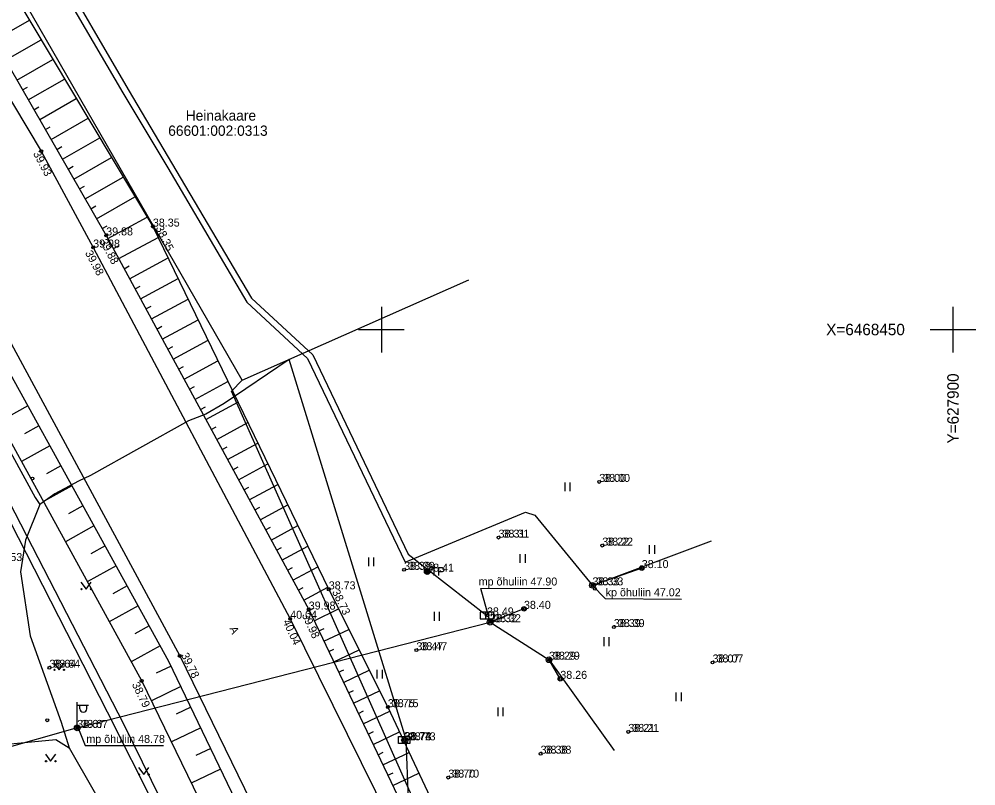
# Model space of a CAD drawing. Extents: x 627548 to 628052, y 6467984 to 6468802.
# Drawn here: x 627818.3 to 627902, y 6468410.1 to 6468477.2 of the extents above; entities that cross this region are included whole.
import ezdxf

# ---------------------------------------------------------------- set-up
doc = ezdxf.new("R2010")
doc.units = 0
for name, color, linetype in [('ABIJOONIS', 7, 'Continuous'), ('ELRAJATISMP', 7, 'Continuous'), ('HALJASTUS', 7, 'Continuous'), ('KORGUS-EH2000', 7, 'Continuous'), ('KPKAABEL', 7, 'Continuous'), ('KPOHULIIN', 7, 'Continuous'), ('MOOTKORG-EH2000', 7, 'Continuous'), ('MOOTMPUNKT', 7, 'Continuous'), ('MPKAABEL', 7, 'Continuous'), ('MPOHULIIN', 7, 'Continuous'), ('PIIR', 7, 'Continuous'), ('POST', 7, 'Continuous'), ('RELJEEF', 7, 'Continuous'), ('SIOHULIIN', 7, 'Continuous'), ('SIRAJATIS', 7, 'Continuous'), ('SITRASS', 7, 'Continuous'), ('TEE', 7, 'Continuous'), ('VORK', 7, 'Continuous')]:
    doc.layers.add(name, color=color, linetype=linetype)

msp = doc.modelspace()

# ---------------------------------------------------------------- linework, layer by layer
at = {"layer": 'ABIJOONIS'}
for points in [[(627859.51, 6468424.378), (627858.71, 6468427.326), (627864.891, 6468427.37)], [(627868.465, 6468427.605), (627869.568, 6468426.466), (627876.261, 6468426.388)], [(627823.446, 6468415.185), (627824.073, 6468413.598), (627830.931, 6468413.598)]]:
    msp.add_lwpolyline(points, dxfattribs=at)
at = {"layer": 'ELRAJATISMP'}
for p, q in [((627859.831, 6468425.271), (627858.637, 6468425.271)), ((627858.637, 6468425.271), (627858.637, 6468424.675)), ((627859.098, 6468425.271), (627859.098, 6468424.675)), ((627859.37, 6468425.271), (627859.37, 6468424.675)), ((627859.831, 6468424.675), (627859.831, 6468425.271)), ((627858.637, 6468424.675), (627859.831, 6468424.675))]:
    msp.add_line(p, q, dxfattribs=at)
at = {"layer": 'HALJASTUS'}
for p, q in [((627866.036, 6468436.597), (627866.036, 6468435.835)), ((627866.491, 6468436.597), (627866.491, 6468435.835)), ((627873.429, 6468431.134), (627873.429, 6468430.373)), ((627873.884, 6468431.134), (627873.884, 6468430.373)), ((627862.112, 6468430.338), (627862.112, 6468429.577)), ((627862.567, 6468430.338), (627862.567, 6468429.577)), ((627848.862, 6468430.053), (627848.862, 6468429.292)), ((627849.317, 6468430.053), (627849.317, 6468429.292)), ((627823.7, 6468427.88), (627824.164, 6468427.273)), ((627824.164, 6468427.273), (627824.609, 6468427.88)), ((627854.606, 6468425.274), (627854.606, 6468424.513)), ((627855.061, 6468425.274), (627855.061, 6468424.513)), ((627869.448, 6468423.055), (627869.448, 6468422.294)), ((627869.903, 6468423.055), (627869.903, 6468422.294)), ((627821.346, 6468420.818), (627821.809, 6468420.212)), ((627821.809, 6468420.212), (627822.255, 6468420.818)), ((627849.601, 6468420.21), (627849.601, 6468419.449)), ((627850.056, 6468420.21), (627850.056, 6468419.449)), ((627875.76, 6468418.218), (627875.76, 6468417.457)), ((627876.215, 6468418.218), (627876.215, 6468417.457)), ((627860.179, 6468416.91), (627860.179, 6468416.148)), ((627860.634, 6468416.91), (627860.634, 6468416.148)), ((627820.606, 6468412.816), (627821.069, 6468412.209)), ((627821.069, 6468412.209), (627821.515, 6468412.816)), ((627828.749, 6468411.659), (627829.213, 6468411.052)), ((627829.213, 6468411.052), (627829.658, 6468411.659))]:
    msp.add_line(p, q, dxfattribs=at)
for centre in [(627823.763, 6468427.273), (627824.591, 6468427.273), (627821.408, 6468420.212), (627822.237, 6468420.212), (627820.668, 6468412.209), (627821.497, 6468412.209), (627828.812, 6468411.052), (627829.64, 6468411.052)]:
    msp.add_circle(centre, 0.055, dxfattribs=at)
at = {"layer": 'KORGUS-EH2000'}
for centre in [(627820.25, 6468465.607), (627832.36, 6468421.427), (627829.03, 6468419.237), (627820.77, 6468415.797)]:
    msp.add_circle(centre, 0.125, dxfattribs=at)
at = {"layer": 'KPKAABEL'}
msp.add_lwpolyline([(627783.664, 6468533.605), (627793.043, 6468521.367), (627800.254, 6468512.234), (627809.598, 6468500.188), (627812.996, 6468495.066), (627814.512, 6468492.199), (627820.805, 6468482.012), (627827.375, 6468470.727), (627831.316, 6468464.148), (627838.215, 6468452.395), (627843.543, 6468447.449), (627852.07, 6468429.637), (627862.617, 6468434.004), (627863.434, 6468433.738), (627868.465, 6468427.605)], dxfattribs=at)
at = {"layer": 'KPOHULIIN'}
msp.add_lwpolyline([(627868.465, 6468427.605), (627878.875, 6468431.498)], dxfattribs=at)
at = {"layer": 'MOOTMPUNKT'}
for centre in [(627830.011, 6468459.01), (627825.927, 6468458.237), (627824.787, 6468457.176), (627819.485, 6468436.954), (627869.054, 6468436.658), (627860.248, 6468431.782), (627869.319, 6468431.085), (627851.985, 6468428.963), (627854.009, 6468428.806), (627872.776, 6468429.115), (627845.394, 6468427.254), (627868.465, 6468427.605), (627868.669, 6468427.3), (627843.642, 6468425.485), (627862.471, 6468425.547), (627842.022, 6468424.68), (627859.234, 6468424.973), (627859.51, 6468424.378), (627859.614, 6468424.591), (627870.333, 6468423.953), (627853.061, 6468421.927), (627864.663, 6468421.096), (627820.956, 6468420.393), (627878.967, 6468420.856), (627865.651, 6468419.421), (627850.56, 6468416.941), (627823.391, 6468415.126), (627823.446, 6468415.185), (627871.595, 6468414.773), (627851.989, 6468414.072), (627852.048, 6468414.037), (627863.924, 6468412.869), (627855.853, 6468410.777)]:
    msp.add_circle(centre, 0.125, dxfattribs=at)
at = {"layer": 'MPKAABEL'}
msp.add_lwpolyline([(627775.609, 6468546.285), (627774.98, 6468546.789), (627774.719, 6468546.18), (627774.691, 6468545.898), (627776.109, 6468544.039), (627784.09, 6468533.941), (627791.949, 6468523.77), (627800.68, 6468512.578), (627810.039, 6468500.512), (627813.461, 6468495.352), (627814.988, 6468492.48), (627821.281, 6468482.301), (627827.852, 6468471.012), (627838.641, 6468452.75), (627843.988, 6468447.781), (627852.328, 6468430.34), (627859.234, 6468424.973)], dxfattribs=at)
at = {"layer": 'MPOHULIIN'}
for q in [(627859.51, 6468424.378), (627808.24, 6468410.853)]:
    msp.add_line((627823.391, 6468415.126), q, dxfattribs=at)
at = {"layer": 'PIIR'}
for p, q in [((627837.82, 6468445.56), (627818.92, 6468478.42)), ((627837.82, 6468445.56), (627857.65, 6468454.352)), ((627836.88, 6468444.6), (627837.82, 6468445.56)), ((627893.5, 6468317.49), (627836.88, 6468444.6)), ((627816.81, 6468434.6), (627826.02, 6468416.53)), ((627826.02, 6468416.53), (627834.21, 6468400.21))]:
    msp.add_line(p, q, dxfattribs=at)
at = {"layer": 'POST'}
for p, q in [((627854.368, 6468429.153), (627854.835, 6468429.153)), ((627854.601, 6468429.153), (627854.601, 6468428.453)), ((627855.001, 6468429.153), (627855.001, 6468428.453)), ((627823.393, 6468415.373), (627823.393, 6468417.373)), ((627823.393, 6468417.123), (627824.393, 6468417.123)), ((627823.62, 6468416.802), (627823.62, 6468417.123)), ((627824.232, 6468416.802), (627824.232, 6468417.123))]:
    msp.add_line(p, q, dxfattribs=at)
for points in [[(627855.001, 6468429.153), (627855.301, 6468429.153), (627855.401, 6468429.12), (627855.435, 6468429.087), (627855.468, 6468429.02), (627855.468, 6468428.92), (627855.435, 6468428.853), (627855.401, 6468428.82), (627855.301, 6468428.787), (627855.001, 6468428.787)], [(627872.776, 6468429.115), (627868.465, 6468427.605)], [(627862.471, 6468425.547), (627859.51, 6468424.378)], [(627865.651, 6468419.421), (627864.663, 6468421.096)]]:
    msp.add_lwpolyline(points, dxfattribs=at)
for centre, radius in [((627854.009, 6468428.806), 0.25), ((627854.009, 6468428.806), 0.225), ((627854.009, 6468428.806), 0.2), ((627854.009, 6468428.806), 0.175), ((627854.009, 6468428.806), 0.15), ((627854.009, 6468428.806), 0.125), ((627854.009, 6468428.806), 0.1), ((627854.009, 6468428.806), 0.075), ((627854.009, 6468428.806), 0.05), ((627854.009, 6468428.806), 0.025), ((627872.776, 6468429.115), 0.2), ((627868.465, 6468427.605), 0.25), ((627862.471, 6468425.547), 0.2), ((627859.51, 6468424.378), 0.25), ((627864.663, 6468421.096), 0.25), ((627864.663, 6468421.096), 0.0234), ((627865.651, 6468419.421), 0.2), ((627823.391, 6468415.126), 0.25), ((627852.048, 6468414.037), 0.25)]:
    msp.add_circle(centre, radius, dxfattribs=at)
msp.add_arc((627823.926, 6468416.802), 0.306, 180, 0, dxfattribs=at)
at = {"layer": 'RELJEEF'}
for p, q in [((627816.126, 6468475.31), (627819.206, 6468477.079)), ((627817.121, 6468473.576), (627820.233, 6468475.362)), ((627818.117, 6468471.841), (627821.26, 6468473.645)), ((627819.113, 6468470.107), (627822.286, 6468471.929)), ((627818.615, 6468470.974), (627819.049, 6468471.223)), ((627820.109, 6468468.372), (627823.313, 6468470.212)), ((627819.611, 6468469.24), (627820.044, 6468469.489)), ((627821.104, 6468466.638), (627824.339, 6468468.495)), ((627820.606, 6468467.505), (627821.04, 6468467.754)), ((627822.1, 6468464.903), (627825.366, 6468466.778)), ((627821.602, 6468465.771), (627822.036, 6468466.02)), ((627823.096, 6468463.169), (627826.392, 6468465.061)), ((627822.598, 6468464.036), (627823.032, 6468464.285)), ((627824.092, 6468461.434), (627827.419, 6468463.345)), ((627823.594, 6468462.302), (627824.027, 6468462.551)), ((627825.087, 6468459.7), (627828.446, 6468461.628)), ((627824.589, 6468460.567), (627825.023, 6468460.816)), ((627826.076, 6468457.961), (627829.523, 6468459.826)), ((627825.585, 6468458.833), (627826.019, 6468459.081)), ((627827.028, 6468456.202), (627830.469, 6468458.064)), ((627826.552, 6468457.082), (627826.992, 6468457.32)), ((627827.979, 6468454.443), (627831.342, 6468456.262)), ((627827.503, 6468455.323), (627827.943, 6468455.561)), ((627828.455, 6468453.564), (627828.895, 6468453.801)), ((627828.931, 6468452.684), (627832.215, 6468454.46)), ((627829.406, 6468451.804), (627829.846, 6468452.042)), ((627829.882, 6468450.925), (627833.088, 6468452.659)), ((627830.834, 6468449.166), (627833.96, 6468450.857)), ((627830.358, 6468450.045), (627830.798, 6468450.283)), ((627831.785, 6468447.406), (627834.833, 6468449.055)), ((627831.309, 6468448.286), (627831.749, 6468448.524)), ((627832.737, 6468445.647), (627835.706, 6468447.253)), ((627832.261, 6468446.527), (627832.701, 6468446.765)), ((627833.688, 6468443.888), (627836.579, 6468445.452)), ((627833.212, 6468444.768), (627833.652, 6468445.006)), ((627819.059, 6468443.315), (627816.59, 6468441.952)), ((627834.164, 6468443.009), (627834.604, 6468443.246)), ((627834.64, 6468442.129), (627837.452, 6468443.65)), ((627820.026, 6468441.565), (627818.788, 6468440.881)), ((627835.115, 6468441.249), (627835.555, 6468441.487)), ((627835.591, 6468440.37), (627838.324, 6468441.848)), ((627820.992, 6468439.814), (627818.511, 6468438.444)), ((627836.067, 6468439.49), (627836.507, 6468439.728)), ((627836.543, 6468438.611), (627839.197, 6468440.046)), ((627821.959, 6468438.063), (627820.715, 6468437.376)), ((627837.018, 6468437.731), (627837.458, 6468437.969)), ((627837.494, 6468436.852), (627840.07, 6468438.245)), ((627822.926, 6468436.312), (627820.433, 6468434.935)), ((627837.97, 6468435.972), (627838.41, 6468436.21)), ((627838.446, 6468435.092), (627840.943, 6468436.443)), ((627823.892, 6468434.561), (627822.643, 6468433.871)), ((627838.921, 6468434.213), (627839.361, 6468434.451)), ((627839.397, 6468433.333), (627841.816, 6468434.641)), ((627824.859, 6468432.81), (627822.354, 6468431.427)), ((627840.349, 6468431.574), (627842.688, 6468432.84)), ((627839.873, 6468432.454), (627840.313, 6468432.691)), ((627825.826, 6468431.059), (627824.57, 6468430.366)), ((627840.824, 6468430.694), (627841.264, 6468430.932)), ((627841.3, 6468429.815), (627843.561, 6468431.038)), ((627826.792, 6468429.308), (627824.276, 6468427.919)), ((627841.776, 6468428.935), (627842.216, 6468429.173)), ((627842.252, 6468428.056), (627844.434, 6468429.236)), ((627827.759, 6468427.558), (627826.498, 6468426.861)), ((627842.727, 6468427.176), (627843.167, 6468427.414)), ((627843.203, 6468426.297), (627845.307, 6468427.434)), ((627828.726, 6468425.807), (627826.197, 6468424.411)), ((627843.675, 6468425.415), (627844.127, 6468425.631)), ((627844.106, 6468424.513), (627846.254, 6468425.538)), ((627829.692, 6468424.056), (627828.425, 6468423.356)), ((627844.537, 6468423.61), (627844.988, 6468423.826)), ((627844.968, 6468422.708), (627847.15, 6468423.749)), ((627830.659, 6468422.305), (627828.119, 6468420.902)), ((627845.399, 6468421.805), (627845.85, 6468422.021)), ((627845.829, 6468420.903), (627848.045, 6468421.961)), ((627831.601, 6468420.542), (627830.301, 6468419.917)), ((627846.26, 6468420.001), (627846.711, 6468420.216)), ((627846.691, 6468419.098), (627848.941, 6468420.172)), ((627832.467, 6468418.739), (627829.877, 6468417.494)), ((627847.122, 6468418.196), (627847.573, 6468418.411)), ((627847.553, 6468417.293), (627849.837, 6468418.384)), ((627833.334, 6468416.936), (627832.042, 6468416.316)), ((627847.983, 6468416.391), (627848.435, 6468416.606)), ((627848.414, 6468415.488), (627850.724, 6468416.591)), ((627834.2, 6468415.133), (627831.625, 6468413.896)), ((627848.845, 6468414.586), (627849.296, 6468414.801)), ((627849.276, 6468413.683), (627851.575, 6468414.781)), ((627835.066, 6468413.331), (627833.782, 6468412.714)), ((627849.707, 6468412.781), (627850.158, 6468412.996)), ((627850.137, 6468411.879), (627852.425, 6468412.971)), ((627835.932, 6468411.528), (627833.373, 6468410.298)), ((627850.568, 6468410.976), (627851.019, 6468411.191)), ((627850.999, 6468410.074), (627853.275, 6468411.16))]:
    msp.add_line(p, q, dxfattribs=at)
for points in [[(627773.759, 6468549.461), (627771.296, 6468547.152), (627771.109, 6468545.291), (627781.198, 6468531.285), (627796.852, 6468507.373), (627811.934, 6468482.612), (627825.927, 6468458.237), (627843.642, 6468425.485), (627854.711, 6468402.298), (627862.101, 6468385.395), (627866.289, 6468377.389), (627871.184, 6468377.936)], [(627772.366, 6468547.143), (627782.438, 6468532.945), (627799.726, 6468507.289), (627814.065, 6468485.677), (627830.011, 6468459.01), (627845.394, 6468427.254), (627850.56, 6468416.941), (627856.095, 6468405.157), (627864.813, 6468385.745), (627868.21, 6468378.879), (627870.923, 6468379.118)], [(627798.462, 6468458.953), (627803.154, 6468462.558), (627806.385, 6468462.787), (627809.612, 6468460.426), (627831.39, 6468420.981), (627849.758, 6468382.754), (627863.845, 6468351.725), (627866.293, 6468345.533)], [(627863.023, 6468347.157), (627861.127, 6468351.404), (627847.089, 6468382.059), (627829.031, 6468419.236), (627807.647, 6468458.279), (627806.821, 6468459.718), (627803.902, 6468460.271), (627798.462, 6468458.953)]]:
    msp.add_lwpolyline(points, dxfattribs=at)
at = {"layer": 'SIOHULIIN'}
for points in [[(627859.51, 6468424.378), (627864.663, 6468421.096)], [(627864.663, 6468421.096), (627870.364, 6468413.15)]]:
    msp.add_lwpolyline(points, dxfattribs=at)
at = {"layer": 'SIRAJATIS'}
msp.add_lwpolyline([(627851.489, 6468414.372), (627852.489, 6468414.372), (627852.489, 6468413.772), (627851.489, 6468413.772)], close=True, dxfattribs=at)
for centre, radius in [((627851.789, 6468414.072), 0.0304), ((627851.789, 6468414.072), 0.029), ((627851.789, 6468414.072), 0.0277), ((627851.789, 6468414.072), 0.0263), ((627851.789, 6468414.072), 0.0249), ((627851.789, 6468414.072), 0.0236), ((627851.789, 6468414.072), 0.0222), ((627851.789, 6468414.072), 0.0209), ((627851.789, 6468414.072), 0.0195), ((627851.789, 6468414.072), 0.0181), ((627851.789, 6468414.072), 0.0168), ((627851.789, 6468414.072), 0.0154), ((627851.789, 6468414.072), 0.014), ((627851.789, 6468414.072), 0.0127), ((627851.789, 6468414.072), 0.0113), ((627851.789, 6468414.072), 0.00996), ((627851.789, 6468414.072), 0.0086), ((627851.789, 6468414.072), 0.00724), ((627851.789, 6468414.072), 0.00587), ((627851.789, 6468414.072), 0.00451), ((627851.789, 6468414.072), 0.00315), ((627851.789, 6468414.072), 0.00179), ((627851.789, 6468414.072), 0.000426), ((627852.189, 6468414.072), 0.0304), ((627852.189, 6468414.072), 0.029), ((627852.189, 6468414.072), 0.0277), ((627852.189, 6468414.072), 0.0263), ((627852.189, 6468414.072), 0.0249), ((627852.189, 6468414.072), 0.0236), ((627852.189, 6468414.072), 0.0222), ((627852.189, 6468414.072), 0.0209), ((627852.189, 6468414.072), 0.0195), ((627852.189, 6468414.072), 0.0181), ((627852.189, 6468414.072), 0.0168), ((627852.189, 6468414.072), 0.0154), ((627852.189, 6468414.072), 0.014), ((627852.189, 6468414.072), 0.0127), ((627852.189, 6468414.072), 0.0113), ((627852.189, 6468414.072), 0.00996), ((627852.189, 6468414.072), 0.0086), ((627852.189, 6468414.072), 0.00724), ((627852.189, 6468414.072), 0.00587), ((627852.189, 6468414.072), 0.00451), ((627852.189, 6468414.072), 0.00315), ((627852.189, 6468414.072), 0.00179), ((627852.189, 6468414.072), 0.000426)]:
    msp.add_circle(centre, radius, dxfattribs=at)
at = {"layer": 'SITRASS'}
for points in [[(627757.217, 6468532.631), (627766.085, 6468521.026), (627772.396, 6468510.946), (627774.395, 6468507.251), (627778.965, 6468498.694), (627784.571, 6468489.044), (627791.177, 6468479.022), (627796.223, 6468473.32), (627799.931, 6468467.58), (627802.003, 6468462.412), (627804.987, 6468458.791), (627809.717, 6468452.583), (627813.499, 6468446.21), (627816.609, 6468440.925), (627819.703, 6468435.299), (627820.118, 6468434.673)], [(627757.269, 6468529.067), (627768.1, 6468513.354), (627774.946, 6468502.943), (627783.7, 6468488.286), (627791.516, 6468476.471), (627794.222, 6468472.86), (627799.922, 6468464.28), (627804.258, 6468458.3), (627808.24, 6468452.254), (627816.937, 6468435.872), (627827.445, 6468415.491), (627836.355, 6468397.304), (627844.956, 6468379.511), (627852.286, 6468362.282), (627856.189, 6468352.574), (627857.741, 6468350.531), (627858.742, 6468350.866)], [(627858.208, 6468326.11), (627860.012, 6468334.798), (627858.052, 6468342.909), (627856.848, 6468350.174), (627857.076, 6468352.201), (627855.207, 6468358.41), (627854.195, 6468363.46), (627853.606, 6468377.354), (627852.171, 6468414.124), (627841.938, 6468447.386), (627836.234, 6468443.524)], [(627836.234, 6468443.524), (627834.646, 6468442.578), (627833.128, 6468441.996), (627824.547, 6468437.221), (627823.498, 6468436.717), (627821.44, 6468435.608), (627820.118, 6468434.673), (627818.856, 6468431.558), (627818.43, 6468428.775), (627819.276, 6468423.196), (627821.974, 6468415.639), (627822.696, 6468413.373)], [(627810.98, 6468412.92), (627816.008, 6468413.596), (627821.508, 6468414.106), (627822.696, 6468413.373), (627824.885, 6468409.551), (627827.286, 6468404.81), (627834.996, 6468390.373), (627839.865, 6468381.11), (627848.975, 6468360.983), (627852.832, 6468354.033), (627854.055, 6468352.951), (627855.398, 6468352.508), (627856.692, 6468352.349), (627857.78, 6468352.478), (627859.022, 6468352.51)]]:
    msp.add_lwpolyline(points, dxfattribs=at)
at = {"layer": 'TEE'}
for points in [[(627773.875, 6468550.47), (627771.331, 6468547.778), (627770.184, 6468544.969), (627779.724, 6468530.382), (627790.194, 6468514.89), (627795.603, 6468506.268), (627810.358, 6468482.16), (627820.252, 6468465.61), (627824.787, 6468457.176), (627842.022, 6468424.68), (627853.219, 6468402.014), (627861.194, 6468384.862), (627867.233, 6468371.168), (627873.073, 6468356.381), (627889.258, 6468318.908), (627892.446, 6468311.434), (627896.87, 6468301.517), (627899.405, 6468301.54), (627901.626, 6468302.361)], [(627796.263, 6468461.011), (627802.362, 6468463.279), (627805.478, 6468464.096), (627807.948, 6468463.607), (627810.898, 6468461.152), (627832.359, 6468421.429), (627850.995, 6468383.192), (627865.917, 6468348.418)]]:
    msp.add_lwpolyline(points, dxfattribs=at)
at = {"layer": 'VORK'}
for p, q in [((627850, 6468452), (627850, 6468448)), ((627900, 6468452), (627900, 6468448)), ((627848, 6468450), (627852, 6468450)), ((627898, 6468450), (627902, 6468450))]:
    msp.add_line(p, q, dxfattribs=at)

# ---------------------------------------------------------------- texts
at = {"layer": 'ABIJOONIS'}
for s, p in [('mp õhuliin 47.90', (627858.514, 6468427.592)), ('kp õhuliin 47.02', (627869.622, 6468426.648)), ('mp õhuliin 48.78', (627824.195, 6468413.811))]:
    msp.add_text(s, height=0.7, dxfattribs=at).set_placement(p)
at = {"layer": 'KORGUS-EH2000'}
for s, rotation, p in [(' 39.93', 298.11917, (627819.387, 6468465.632)), ('38.35', 295.50292, (627830.236, 6468458.896)), ('39.88', 297.73882, (627825.357, 6468457.705)), ('39.98', 297.96464, (627824.056, 6468456.707)), ('38.73', 295.94859, (627845.668, 6468427.041)), ('40.04', 294.59394, (627841.363, 6468424.435)), ('39.98', 294.76631, (627843.025, 6468425.004)), (' 39.78', 295.98374, (627832.346, 6468421.736)), (' 38.79', 295.90726, (627828.044, 6468419.17))]:
    msp.add_text(s, height=0.7, rotation=rotation, dxfattribs=at).set_placement(p)
for s, p in [('38.00', (627869.404, 6468436.658)), ('38.31', (627860.598, 6468431.782)), ('38.22', (627869.669, 6468431.085)), ('38.53', (627816.241, 6468429.733)), ('38.39', (627852.335, 6468428.963)), ('38.33', (627868.815, 6468427.605)), ('38.32', (627859.86, 6468424.378)), ('38.39', (627870.683, 6468423.953)), ('38.47', (627853.411, 6468421.927)), ('38.64', (627821.306, 6468420.393)), ('38.29', (627865.013, 6468421.096)), ('38.07', (627879.317, 6468420.856)), ('38.75', (627850.91, 6468416.941)), ('38.67', (627823.741, 6468415.126)), ('38.21', (627871.945, 6468414.773)), ('38.73', (627852.398, 6468414.037)), ('38.38', (627864.274, 6468412.869)), ('38.70', (627856.203, 6468410.777))]:
    msp.add_text(s, height=0.7, dxfattribs=at).set_placement(p)
at = {"layer": 'MOOTKORG-EH2000'}
for s, p in [('38.35', (627830.011, 6468459.01)), ('39.88', (627825.927, 6468458.237)), ('39.98', (627824.787, 6468457.176)), ('38.00', (627869.054, 6468436.658)), ('38.31', (627860.248, 6468431.782)), ('38.22', (627869.319, 6468431.085)), ('38.39', (627851.985, 6468428.963)), ('38.41', (627854.009, 6468428.806)), ('38.10', (627872.776, 6468429.115)), ('38.73', (627845.394, 6468427.254)), ('38.33', (627868.465, 6468427.605)), ('39.98', (627843.642, 6468425.485)), ('38.40', (627862.471, 6468425.547)), ('40.04', (627842.022, 6468424.68)), ('38.49', (627859.234, 6468424.973)), ('38.32', (627859.51, 6468424.378)), ('38.39', (627870.333, 6468423.953)), ('38.47', (627853.061, 6468421.927)), ('38.64', (627820.956, 6468420.393)), ('38.29', (627864.663, 6468421.096)), ('38.07', (627878.967, 6468420.856)), ('38.26', (627865.651, 6468419.421)), ('38.75', (627850.56, 6468416.941)), ('38.67', (627823.391, 6468415.126)), ('38.21', (627871.595, 6468414.773)), ('38.74', (627851.989, 6468414.072)), ('38.73', (627852.048, 6468414.037)), ('38.38', (627863.924, 6468412.869)), ('38.70', (627855.853, 6468410.777))]:
    msp.add_text(s, height=0.7, dxfattribs=at).set_placement(p)
at = {"layer": 'PIIR'}
for s, p in [('Heinakaare', (627832.883, 6468468.286)), ('66601:002:0313', (627831.352, 6468466.955))]:
    msp.add_text(s, height=0.9, dxfattribs=at).set_placement(p)
at = {"layer": 'TEE'}
msp.add_text('A', height=0.7, rotation=293.00994, dxfattribs=at).set_placement((627836.697, 6468423.842))
at = {"layer": 'VORK'}
msp.add_text('X=6468450 ', height=1, dxfattribs=at).set_placement((627888.908, 6468449.5))
msp.add_text('Y=627900 ', height=1, rotation=90, dxfattribs=at).set_placement((627900.5, 6468440.021))

doc.saveas('drawing.dxf')
